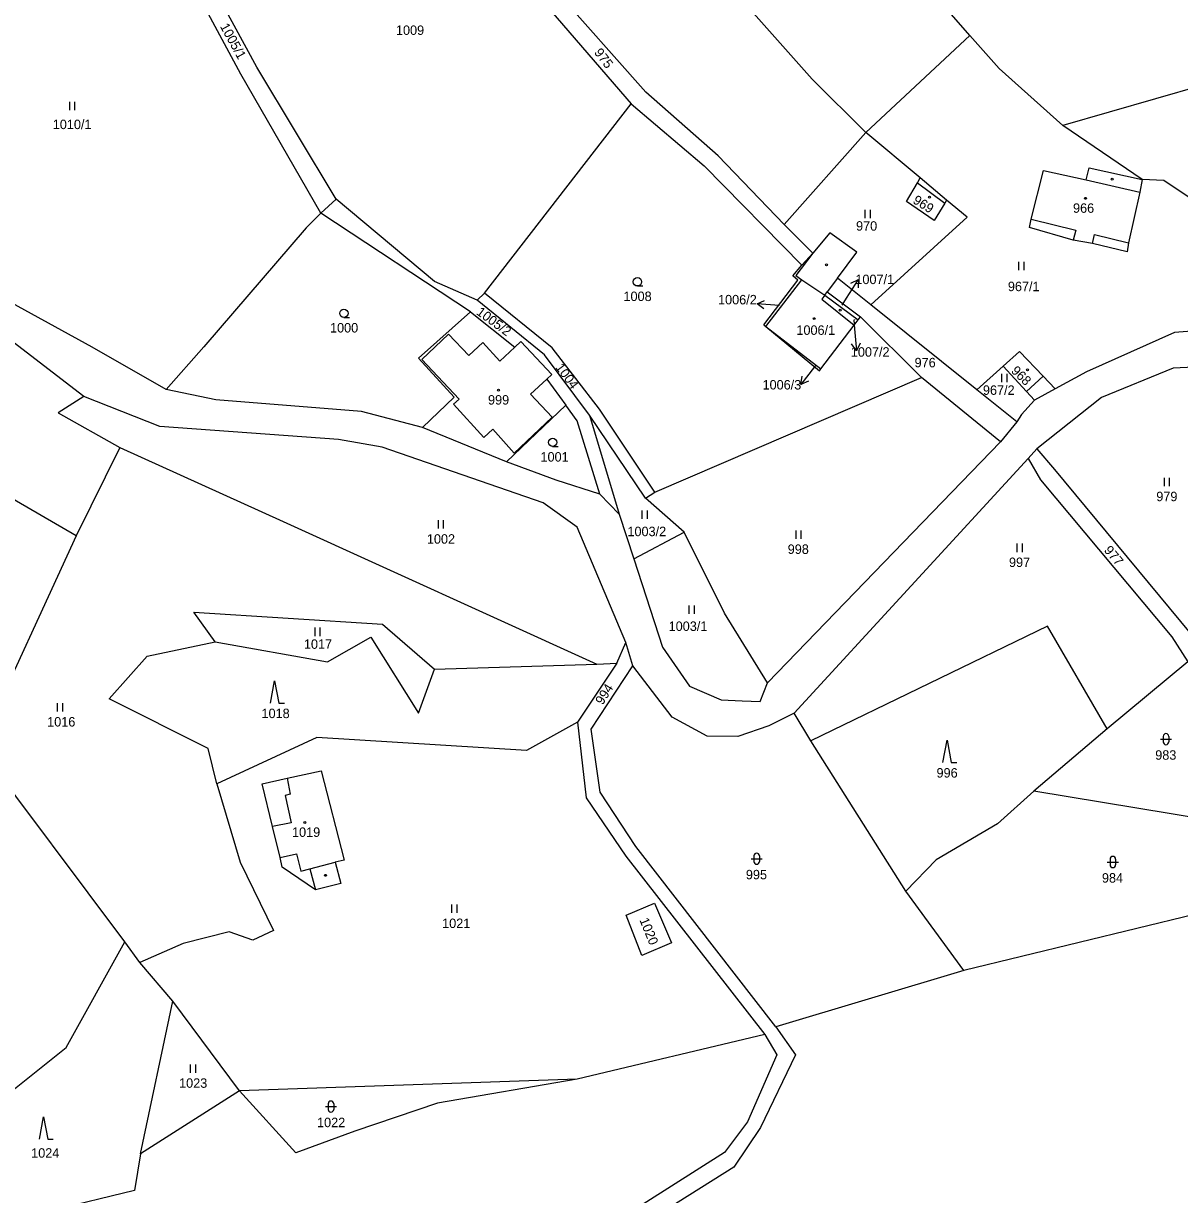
# Model space of a CAD drawing. Extents: x -670359 to -668019, y -978807 to -976674.
# Drawn here: x -669783.1 to -669575.5, y -977781.2 to -977570.9 of the extents above; entities that cross this region are included whole.
import ezdxf

# ---------------------------------------------------------------- set-up
doc = ezdxf.new("R2010")
doc.units = 0
for name, color, linetype in [('Hranice parcel', 7, 'Continuous'), ('Parcelní čísla', 7, 'Continuous'), ('Vnitřní kresba', 7, 'Continuous'), ('Značky budov', 7, 'Continuous'), ('Značky kultur', 7, 'Continuous')]:
    doc.layers.add(name, color=color, linetype=linetype)

msp = doc.modelspace()

# ---------------------------------------------------------------- linework, layer by layer
at = {"layer": 'Hranice parcel'}
for p, q in [((-669702.8, -977622.71), (-669694.86, -977629.03)), ((-669694.86, -977629.03), (-669693.79, -977628.05)), ((-669693.79, -977628.05), (-669688.21, -977633.93)), ((-669688.21, -977633.93), (-669689.13, -977634.79)), ((-669689.13, -977634.79), (-669685.71, -977639.46))]:
    msp.add_line(p, q, dxfattribs=at)
for points in [[(-669744.06, -977580.04), (-669759.08, -977552.08)], [(-669741.19, -977578.75), (-669756.29, -977550.87)], [(-669613.14, -977573.11), (-669632.98, -977550.37)], [(-669641.45, -977580.95), (-669662.61, -977557.1)], [(-669671.35, -977583.28), (-669687.92, -977564.52)], [(-669690.63, -977565.98), (-669673.98, -977585.38)], [(-669631.8, -977590.48), (-669613.14, -977573.11)], [(-669607.88, -977578.99), (-669613.14, -977573.11)], [(-669726.9, -977602.47), (-669741.19, -977578.75)], [(-669596.46, -977589.23), (-669607.88, -977578.99)], [(-669729.69, -977604.97), (-669744.06, -977580.04)], [(-669631.8, -977590.48), (-669641.45, -977580.95)], [(-669563.17, -977579.68), (-669596.46, -977589.23)], [(-669658.33, -977594.71), (-669671.35, -977583.28)], [(-669700.29, -977619.32), (-669673.98, -977585.38)], [(-669673.98, -977585.38), (-669660.88, -977596.49)], [(-669582.18, -977598.97), (-669596.46, -977589.23)], [(-669631.8, -977590.48), (-669646.51, -977607.03)], [(-669622.05, -977598.67), (-669631.8, -977590.48)], [(-669646.51, -977607.03), (-669658.33, -977594.71)], [(-669660.88, -977596.49), (-669643.3, -977614.32)], [(-669602.13, -977606.04), (-669599.94, -977597.32)], [(-669599.94, -977597.32), (-669592.25, -977599.03)], [(-669592.25, -977599.03), (-669591.7, -977596.87)], [(-669591.7, -977596.87), (-669582.18, -977598.97)], [(-669624.54, -977602.9), (-669622.56, -977599.53)], [(-669622.56, -977599.53), (-669622.05, -977598.67)], [(-669617.33, -977602.63), (-669622.05, -977598.67)], [(-669582.18, -977598.97), (-669582.61, -977601.23)], [(-669578.34, -977599.11), (-669582.18, -977598.97)], [(-669546.47, -977620.34), (-669578.34, -977599.11)], [(-669729.69, -977604.97), (-669726.9, -977602.47)], [(-669709.26, -977617.28), (-669726.9, -977602.47)], [(-669617.33, -977602.63), (-669617.66, -977603.18)], [(-669613.65, -977605.71), (-669617.33, -977602.63)], [(-669582.61, -977601.23), (-669584.67, -977610.34)], [(-669619.56, -977606.31), (-669624.54, -977602.9)], [(-669617.66, -977603.18), (-669619.56, -977606.31)], [(-669729.69, -977604.97), (-669732.31, -977607.62)], [(-669702.8, -977622.71), (-669729.69, -977604.97)], [(-669630.9, -977621.45), (-669613.65, -977605.71)], [(-669602.44, -977607.57), (-669602.13, -977606.04)], [(-669732.31, -977607.62), (-669750.67, -977628.99)], [(-669641.36, -977612.19), (-669646.51, -977607.03)], [(-669638.26, -977608.5), (-669641.36, -977612.19)], [(-669633.45, -977611.99), (-669638.26, -977608.5)], [(-669594.59, -977609.84), (-669602.44, -977607.57)], [(-669591.15, -977610.45), (-669594.59, -977609.84)], [(-669584.91, -977611.94), (-669591.15, -977610.45)], [(-669584.67, -977610.34), (-669584.91, -977611.94)], [(-669641.36, -977612.19), (-669644.37, -977616.17)], [(-669643.3, -977614.32), (-669641.36, -977612.19)], [(-669636.94, -977616.64), (-669633.45, -977611.99)], [(-669644.94, -977616.21), (-669643.3, -977614.32)], [(-669701.58, -977620.62), (-669709.26, -977617.28)], [(-669650.15, -977625.03), (-669644.06, -977617)], [(-669649.75, -977625.36), (-669643.33, -977616.96)], [(-669644.06, -977617), (-669644.94, -977616.21)], [(-669644.37, -977616.17), (-669643.33, -977616.96)], [(-669636.94, -977616.64), (-669638.77, -977619.13)], [(-669630.9, -977621.45), (-669636.94, -977616.64)], [(-669770.74, -977629.03), (-669788.31, -977619.38)], [(-669701.58, -977620.62), (-669700.29, -977619.32)], [(-669688.13, -977629.14), (-669700.29, -977619.32)], [(-669639.2, -977619.73), (-669638.77, -977619.13)], [(-669638.77, -977619.13), (-669632.78, -977623.59)], [(-669689.55, -977630.42), (-669701.58, -977620.62)], [(-669639.2, -977619.73), (-669639.7, -977620.4), (-669633.91, -977625.07)], [(-669639.2, -977619.73), (-669633.19, -977624.13)], [(-669611.88, -977636.68), (-669630.9, -977621.45)], [(-669702.8, -977622.71), (-669712.12, -977630.99)], [(-669633.19, -977624.13), (-669632.78, -977623.59)], [(-669632.78, -977623.59), (-669621.84, -977634.48)], [(-669650.15, -977625.03), (-669649.75, -977625.36)], [(-669649.75, -977625.36), (-669644.66, -977629.57), (-669640.16, -977633.27)], [(-669649.75, -977625.36), (-669639.91, -977632.94)], [(-669639.91, -977632.94), (-669633.91, -977625.07)], [(-669633.91, -977625.07), (-669633.19, -977624.13)], [(-669562.52, -977625.31), (-669576.43, -977626.43)], [(-669576.43, -977626.43), (-669592.23, -977633.48)], [(-669772.22, -977637.91), (-669784.93, -977628.12)], [(-669757.47, -977636.62), (-669770.74, -977629.03)], [(-669750.67, -977628.99), (-669757.47, -977636.62)], [(-669679.67, -977640.17), (-669688.13, -977629.14)], [(-669607.19, -977632.45), (-669604.24, -977629.79)], [(-669604.24, -977629.79), (-669599.98, -977634.24)], [(-669712.12, -977630.99), (-669705.76, -977637.99)], [(-669681.42, -977641.23), (-669689.55, -977630.42)], [(-669564, -977632.19), (-669576.64, -977632.82)], [(-669640.16, -977633.27), (-669639.91, -977632.94)], [(-669611.88, -977636.68), (-669607.19, -977632.45)], [(-669603, -977636.98), (-669607.19, -977632.45)], [(-669599.98, -977634.24), (-669597.8, -977636.52)], [(-669592.23, -977633.48), (-669597.8, -977636.52)], [(-669576.64, -977632.82), (-669589.48, -977638.09)], [(-669669.73, -977655.05), (-669621.84, -977634.48)], [(-669607.67, -977646.03), (-669621.84, -977634.48)], [(-669772.22, -977637.91), (-669776.84, -977640.81)], [(-669758.59, -977643.26), (-669772.22, -977637.91)], [(-669748.54, -977638.48), (-669757.47, -977636.62)], [(-669722.38, -977640.57), (-669748.54, -977638.48)], [(-669705.76, -977637.99), (-669711.41, -977643.46)], [(-669604.71, -977642.43), (-669611.88, -977636.68)], [(-669601.54, -977638.56), (-669603, -977636.98)], [(-669597.8, -977636.52), (-669601.54, -977638.56)], [(-669589.48, -977638.09), (-669601.11, -977647.27)], [(-669716.21, -977642.21), (-669722.38, -977640.57)], [(-669685.71, -977639.46), (-669696.32, -977649.6)], [(-669683.67, -977642.25), (-669685.71, -977639.46)], [(-669669.73, -977655.05), (-669679.67, -977640.17)], [(-669601.54, -977638.56), (-669603.86, -977641.14)], [(-669773.6, -977662.93), (-669808.82, -977642.52)], [(-669776.84, -977640.81), (-669765.77, -977647.06)], [(-669711.41, -977643.46), (-669716.21, -977642.21)], [(-669679.6, -977655.41), (-669683.67, -977642.25)], [(-669671.39, -977656.17), (-669681.42, -977641.23)], [(-669681.42, -977641.23), (-669676.14, -977658.99)], [(-669604.71, -977642.43), (-669607.67, -977646.03)], [(-669603.86, -977641.14), (-669604.71, -977642.43)], [(-669726.51, -977645.62), (-669758.59, -977643.26)], [(-669696.32, -977649.6), (-669711.41, -977643.46)], [(-669718.67, -977647.02), (-669726.51, -977645.62)], [(-669607.67, -977646.03), (-669649.47, -977689.27)], [(-669765.77, -977647.06), (-669773.6, -977662.93)], [(-669765.77, -977647.06), (-669736.42, -977660.32)], [(-669689.74, -977656.99), (-669718.67, -977647.02)], [(-669602.7, -977649.04), (-669644.68, -977694.76)], [(-669601.11, -977647.27), (-669602.7, -977649.04)], [(-669602.7, -977649.04), (-669600.44, -977652.86)], [(-669601.11, -977647.27), (-669597.97, -977651.01)], [(-669687.45, -977652.9), (-669696.32, -977649.6)], [(-669597.97, -977651.01), (-669573.58, -977680.35)], [(-669679.6, -977655.41), (-669687.45, -977652.9)], [(-669600.44, -977652.86), (-669576.86, -977681.01)], [(-669671.39, -977656.17), (-669669.73, -977655.05)], [(-669683.64, -977661.35), (-669689.74, -977656.99)], [(-669676.14, -977658.99), (-669679.6, -977655.41)], [(-669664.46, -977662.23), (-669671.39, -977656.17)], [(-669676.14, -977658.99), (-669673.51, -977667.04)], [(-669736.42, -977660.32), (-669680.15, -977685.94)], [(-669674.89, -977682.08), (-669683.64, -977661.35)], [(-669773.6, -977662.93), (-669791.07, -977700.83)], [(-669673.51, -977667.04), (-669664.46, -977662.23)], [(-669657.23, -977676.79), (-669664.46, -977662.23)], [(-669673.51, -977667.04), (-669668.33, -977682.92)], [(-669748.63, -977681.96), (-669752.49, -977676.63)], [(-669752.49, -977676.63), (-669718.58, -977678.74)], [(-669649.47, -977689.27), (-669657.23, -977676.79)], [(-669718.58, -977678.74), (-669709.26, -977686.84)], [(-669599.18, -977679.15), (-669641.69, -977699.7)], [(-669588.52, -977697.54), (-669599.18, -977679.15)], [(-669760.85, -977684.51), (-669748.63, -977681.96)], [(-669748.63, -977681.96), (-669728.46, -977685.51)], [(-669728.46, -977685.51), (-669720.72, -977681.07)], [(-669720.72, -977681.07), (-669712.17, -977694.77)], [(-669676.55, -977685.76), (-669674.89, -977682.08)], [(-669673.67, -977686.22), (-669674.89, -977682.08)], [(-669576.86, -977681.01), (-669574.03, -977685.55)], [(-669767.69, -977692.14), (-669760.85, -977684.51)], [(-669668.33, -977682.92), (-669663.5, -977689.92)], [(-669712.17, -977694.77), (-669709.26, -977686.84)], [(-669709.26, -977686.84), (-669680.15, -977685.94)], [(-669676.55, -977685.76), (-669683.61, -977696.35)], [(-669681.13, -977697.62), (-669673.67, -977686.22)], [(-669680.15, -977685.94), (-669676.55, -977685.76)], [(-669666.58, -977695.45), (-669673.67, -977686.22)], [(-669574.03, -977685.55), (-669588.52, -977697.54)], [(-669663.5, -977689.92), (-669657.8, -977692.36)], [(-669650.77, -977692.64), (-669649.47, -977689.27)], [(-669749.88, -977701.06), (-669767.69, -977692.14)], [(-669657.8, -977692.36), (-669654.05, -977692.5)], [(-669654.05, -977692.5), (-669650.77, -977692.64)], [(-669644.68, -977694.76), (-669649.22, -977697.03)], [(-669641.69, -977699.7), (-669644.68, -977694.76)], [(-669683.61, -977696.35), (-669692.78, -977701.44)], [(-669683.61, -977696.35), (-669682.02, -977709.93)], [(-669660.33, -977698.85), (-669666.58, -977695.45)], [(-669649.22, -977697.03), (-669654.81, -977698.9)], [(-669730.38, -977699.11), (-669748.33, -977707.45)], [(-669692.78, -977701.44), (-669730.38, -977699.11)], [(-669679.55, -977708.95), (-669681.13, -977697.62)], [(-669654.81, -977698.9), (-669660.33, -977698.85)], [(-669588.52, -977697.54), (-669601.66, -977708.73)], [(-669764.89, -977735.76), (-669791.07, -977700.83)], [(-669748.33, -977707.45), (-669749.88, -977701.06)], [(-669624.67, -977726.69), (-669641.69, -977699.7)], [(-669735.7, -977706.41), (-669729.63, -977705.1)], [(-669729.63, -977705.1), (-669725.51, -977721.1)], [(-669748.33, -977707.45), (-669744.18, -977721.49)], [(-669740.23, -977707.44), (-669735.7, -977706.41)], [(-669738.37, -977715.06), (-669740.23, -977707.44)], [(-669682.02, -977709.93), (-669674.93, -977720.43)], [(-669673.1, -977718.67), (-669679.55, -977708.95)], [(-669601.66, -977708.73), (-669608.18, -977714.6)], [(-669564.68, -977714.82), (-669601.66, -977708.73)], [(-669736.98, -977720.65), (-669738.37, -977715.06)], [(-669608.18, -977714.6), (-669619.18, -977721.06)], [(-669674.93, -977720.43), (-669649.96, -977752.41)], [(-669647.97, -977751.04), (-669673.1, -977718.67)], [(-669744.18, -977721.49), (-669738.19, -977733.76)], [(-669736.65, -977722.4), (-669736.98, -977720.65)], [(-669730.65, -977726.47), (-669736.65, -977722.4)], [(-669725.51, -977721.1), (-669727.09, -977721.49)], [(-669727.09, -977721.49), (-669726.1, -977725.33)], [(-669619.18, -977721.06), (-669624.67, -977726.69)], [(-669726.1, -977725.33), (-669730.65, -977726.47)], [(-669614.2, -977740.93), (-669624.67, -977726.69)], [(-669674.87, -977730.98), (-669669.76, -977728.87)], [(-669669.76, -977728.87), (-669666.69, -977735.97)], [(-669562.44, -977728.39), (-669614.2, -977740.93)], [(-669672.03, -977738.24), (-669674.87, -977730.98)], [(-669746.11, -977733.97), (-669754.41, -977736.09)], [(-669741.86, -977735.46), (-669746.11, -977733.97)], [(-669738.19, -977733.76), (-669741.86, -977735.46)], [(-669775.42, -977754.76), (-669764.89, -977735.76)], [(-669762.15, -977739.49), (-669764.89, -977735.76)], [(-669754.41, -977736.09), (-669762.15, -977739.49)], [(-669666.69, -977735.97), (-669672.03, -977738.24)], [(-669756.28, -977746.41), (-669762.15, -977739.49)], [(-669614.2, -977740.93), (-669647.97, -977751.04)], [(-669762.05, -977773.86), (-669756.28, -977746.41)], [(-669744.31, -977762.55), (-669756.28, -977746.41)], [(-669647.97, -977751.04), (-669644.43, -977756.05)], [(-669649.96, -977752.41), (-669683.67, -977760.42)], [(-669649.96, -977752.41), (-669647.78, -977756.07)], [(-669786.17, -977763.37), (-669775.42, -977754.76)], [(-669647.78, -977756.07), (-669653.08, -977768.09)], [(-669644.43, -977756.05), (-669650.75, -977769.12)], [(-669683.67, -977760.42), (-669744.31, -977762.55)], [(-669683.67, -977760.42), (-669708.75, -977764.75)], [(-669744.31, -977762.55), (-669762.05, -977773.86)], [(-669734.16, -977773.67), (-669744.31, -977762.55)], [(-669708.75, -977764.75), (-669723.6, -977769.79)], [(-669653.08, -977768.09), (-669657.21, -977773.63)], [(-669723.6, -977769.79), (-669734.16, -977773.67)], [(-669650.75, -977769.12), (-669655.51, -977776.26)], [(-669762.05, -977773.86), (-669763.13, -977780.42)], [(-669657.21, -977773.63), (-669694.58, -977797.35)], [(-669655.51, -977776.26), (-669692.73, -977799.65)], [(-669763.13, -977780.42), (-669777.91, -977784.02)]]:
    msp.add_lwpolyline(points, dxfattribs=at)
at = {"layer": 'Parcelní čísla'}
for p, q in [((-669634.5, -977617.57), (-669633.17, -977616.87)), ((-669650.12, -977622.13), (-669651.36, -977621.29)), ((-669636.08, -977621.53), (-669635.29, -977620.26)), ((-669633.96, -977624.11), (-669633.83, -977625.72)), ((-669632.87, -977628.35), (-669633.52, -977629.71)), ((-669640.88, -977632.4), (-669641.02, -977632.58)), ((-669642.09, -977635.17), (-669643.48, -977635.73))]:
    msp.add_line(p, q, dxfattribs=at)
for points in [[(-669635.29, -977620.26), (-669633.17, -977616.87), (-669633.22, -977618.37)], [(-669647.37, -977621.58), (-669651.36, -977621.29), (-669650.01, -977620.64)], [(-669633.83, -977625.72), (-669633.52, -977629.71), (-669634.37, -977628.47)], [(-669641.02, -977632.58), (-669643.48, -977635.73), (-669643.27, -977634.25)]]:
    msp.add_lwpolyline(points, dxfattribs=at)
at = {"layer": 'Vnitřní kresba'}
for points in [[(-669622.56, -977599.53), (-669617.66, -977603.18)], [(-669592.25, -977599.03), (-669582.61, -977601.23)], [(-669602.13, -977606.04), (-669594.14, -977608.01)], [(-669594.14, -977608.01), (-669594.59, -977609.84)], [(-669591.15, -977610.45), (-669590.75, -977608.84)], [(-669590.75, -977608.84), (-669584.67, -977610.34)], [(-669643.33, -977616.96), (-669639.2, -977619.73)], [(-669711.53, -977631.23), (-669706.74, -977626.68)], [(-669706.74, -977626.68), (-669703.12, -977630.56), (-669700.6, -977628.22)], [(-669700.6, -977628.22), (-669697.54, -977631.53)], [(-669697.54, -977631.53), (-669694.86, -977629.03)], [(-669711.53, -977631.23), (-669704.83, -977638.4)], [(-669603, -977636.98), (-669599.98, -977634.24)], [(-669692.01, -977637.46), (-669689.13, -977634.79)], [(-669704.83, -977638.4), (-669705.85, -977639.3)], [(-669692.01, -977637.46), (-669688.16, -977641.61)], [(-669705.85, -977639.3), (-669700.4, -977645.23)], [(-669694.95, -977648.05), (-669688.16, -977641.61)], [(-669700.4, -977645.23), (-669698.82, -977643.73)], [(-669698.82, -977643.73), (-669694.95, -977648.05)], [(-669735.7, -977706.41), (-669735.2, -977709.29)], [(-669735.2, -977709.29), (-669736.08, -977709.53)], [(-669736.08, -977709.53), (-669735.02, -977714.4)], [(-669735.02, -977714.4), (-669738.37, -977715.06)], [(-669736.98, -977720.65), (-669734.03, -977719.99)], [(-669734.03, -977719.99), (-669733.26, -977723.08)], [(-669731.63, -977722.66), (-669727.09, -977721.49)], [(-669733.26, -977723.08), (-669731.63, -977722.66)], [(-669731.63, -977722.66), (-669730.65, -977726.47)]]:
    msp.add_lwpolyline(points, dxfattribs=at)
at = {"layer": 'Značky budov'}
for centre in [(-669620.4, -977602.11), (-669592.36, -977602.32), (-669641.08, -977623.92), (-669602.81, -977633.12), (-669697.77, -977636.75), (-669732.53, -977714.35)]:
    msp.add_circle(centre, 0.175, dxfattribs=at)
at = {"layer": 'Značky kultur'}
for p, q in [((-669774.82, -977585), (-669774.82, -977586.5)), ((-669773.82, -977586.5), (-669773.82, -977585)), ((-669631.98, -977604.36), (-669631.98, -977605.86)), ((-669630.98, -977605.86), (-669630.98, -977604.36)), ((-669604.4, -977613.73), (-669604.4, -977615.23)), ((-669603.4, -977615.23), (-669603.4, -977613.73)), ((-669672.84, -977618.06), (-669671.84, -977618.06)), ((-669725.53, -977623.71), (-669724.53, -977623.71)), ((-669607.46, -977633.81), (-669607.46, -977635.31)), ((-669606.46, -977635.31), (-669606.46, -977633.81)), ((-669688.06, -977646.88), (-669687.06, -977646.88)), ((-669578.28, -977652.49), (-669578.28, -977653.99)), ((-669577.28, -977653.99), (-669577.28, -977652.49)), ((-669672.05, -977658.38), (-669672.05, -977659.88)), ((-669671.05, -977659.88), (-669671.05, -977658.38)), ((-669708.64, -977660.12), (-669708.64, -977661.62)), ((-669707.64, -977661.62), (-669707.64, -977660.12)), ((-669644.42, -977661.95), (-669644.42, -977663.45)), ((-669643.42, -977663.45), (-669643.42, -977661.95)), ((-669604.69, -977664.31), (-669604.69, -977665.81)), ((-669603.69, -977665.81), (-669603.69, -977664.31)), ((-669663.59, -977675.4), (-669663.59, -977676.9)), ((-669662.59, -977676.9), (-669662.59, -977675.4)), ((-669730.77, -977679.39), (-669730.77, -977680.89)), ((-669729.77, -977680.89), (-669729.77, -977679.39)), ((-669777, -977692.94), (-669777, -977694.44)), ((-669776, -977694.44), (-669776, -977692.94)), ((-669578.93, -977699.4), (-669576.93, -977699.4)), ((-669578.43, -977698.9), (-669578.43, -977699.9)), ((-669577.43, -977698.9), (-669577.43, -977699.9)), ((-669651.93, -977720.37), (-669651.93, -977721.37)), ((-669650.93, -977720.37), (-669650.93, -977721.37)), ((-669652.43, -977720.87), (-669650.43, -977720.87)), ((-669588.47, -977721.46), (-669586.47, -977721.46)), ((-669587.97, -977720.96), (-669587.97, -977721.96)), ((-669586.97, -977720.96), (-669586.97, -977721.96)), ((-669706.22, -977729.11), (-669706.22, -977730.61)), ((-669705.22, -977730.61), (-669705.22, -977729.11)), ((-669753.13, -977757.79), (-669753.13, -977759.29)), ((-669752.13, -977759.29), (-669752.13, -977757.79)), ((-669728.86, -977765.36), (-669726.86, -977765.36)), ((-669728.36, -977764.86), (-669728.36, -977765.86)), ((-669727.36, -977764.86), (-669727.36, -977765.86))]:
    msp.add_line(p, q, dxfattribs=at)
for points in [[(-669738.72, -977692.93), (-669737.97, -977688.93), (-669737.22, -977692.93), (-669736.22, -977692.93)], [(-669617.99, -977703.6), (-669617.24, -977699.6), (-669616.49, -977703.6), (-669615.49, -977703.6)], [(-669780.21, -977771.23), (-669779.46, -977767.23), (-669778.71, -977771.23), (-669777.71, -977771.23)]]:
    msp.add_lwpolyline(points, dxfattribs=at)
for centre, radius in [((-669587.62, -977598.9), 0.175), ((-669620.4, -977602.11), 0.175), ((-669592.36, -977602.32), 0.175), ((-669638.87, -977614.27), 0.175), ((-669672.84, -977617.31), 0.75), ((-669725.53, -977622.96), 0.75), ((-669641.08, -977623.92), 0.175), ((-669636.43, -977622.39), 0.175), ((-669602.81, -977633.12), 0.175), ((-669697.77, -977636.75), 0.175), ((-669688.06, -977646.13), 0.75), ((-669732.53, -977714.35), 0.175), ((-669728.82, -977723.85), 0.175)]:
    msp.add_circle(centre, radius, dxfattribs=at)
for centre, start, end in [((-669577.93, -977698.9), 0, 180), ((-669577.93, -977699.9), 180, 0), ((-669651.43, -977720.37), 0, 180), ((-669587.47, -977720.96), 0, 180), ((-669651.43, -977721.37), 180, 0), ((-669587.47, -977721.96), 180, 0), ((-669727.86, -977764.86), 0, 180), ((-669727.86, -977765.86), 180, 0)]:
    msp.add_arc(centre, 0.5, start, end, dxfattribs=at)

# ---------------------------------------------------------------- texts
at = {"layer": 'Parcelní čísla'}
for s, rotation, p in [('1005/1', 298.8196, (-669747.84, -977571.45)), ('975', 307.1041, (-669680.69, -977576.16)), ('969', 328.0999, (-669623.53, -977603.08)), ('1005/2', 323.5837, (-669701.89, -977623.04)), ('1004', 306.7097, (-669687.65, -977632.69)), ('968', 315.9935, (-669605.86, -977633.44)), ('977', 310.1148, (-669589.17, -977665.55)), ('994', 58.1361, (-669679.08, -977693.38)), ('1020', 292.2936, (-669672.5, -977731.86))]:
    msp.add_text(s, height=1.7, rotation=rotation, dxfattribs=at).set_placement(p)
for s, height, p in [('1009', 1.7, (-669716.19, -977572.99)), ('1010/1', 1.7, (-669777.81, -977589.9)), ('966', 1.7, (-669594.62, -977604.92)), ('970', 1.7, (-669633.58, -977608.13)), ('1007/1', 1.7, (-669633.7, -977617.72)), ('967/1', 1.7, (-669606.32, -977618.99)), ('1008', 1.7, (-669675.34, -977620.76)), ('1006/2', 1.7, (-669658.36, -977621.36)), ('1006/2', 0.1, (-669647.37, -977621.58)), ('1007/1', 0.1, (-669636.08, -977621.53)), ('1000', 1.7, (-669728.03, -977626.41)), ('1006/1', 1.7, (-669644.29, -977626.83)), ('1007/2', 0.1, (-669633.96, -977624.11)), ('1007/2', 1.7, (-669634.52, -977630.75)), ('976', 1.7, (-669623.07, -977632.66)), ('1006/3', 0.1, (-669640.88, -977632.4)), ('1006/3', 1.7, (-669650.37, -977636.64)), ('967/2', 1.7, (-669610.8, -977637.6)), ('999', 1.7, (-669699.66, -977639.35)), ('1001', 1.7, (-669690.24, -977649.58)), ('979', 1.7, (-669579.67, -977656.69)), ('1003/2', 1.7, (-669674.63, -977662.97)), ('1002', 1.7, (-669710.64, -977664.32)), ('998', 1.7, (-669645.85, -977666.15)), ('997', 1.7, (-669606.12, -977668.51)), ('1003/1', 1.7, (-669667.23, -977679.98)), ('1017', 1.7, (-669732.72, -977683.19)), ('1018', 1.7, (-669740.33, -977695.63)), ('1016', 1.7, (-669778.82, -977697.14)), ('983', 1.7, (-669579.86, -977703.1)), ('996', 1.7, (-669619.13, -977706.3)), ('1019', 1.7, (-669734.85, -977716.95)), ('995', 1.7, (-669653.36, -977724.57)), ('984', 1.7, (-669589.43, -977725.16)), ('1021', 1.7, (-669707.9, -977733.31)), ('1023', 1.7, (-669755.13, -977761.99)), ('1022', 1.7, (-669730.36, -977769.06)), ('1024', 1.7, (-669781.69, -977774.54))]:
    msp.add_text(s, height=height, dxfattribs=at).set_placement(p)

doc.saveas('drawing.dxf')
